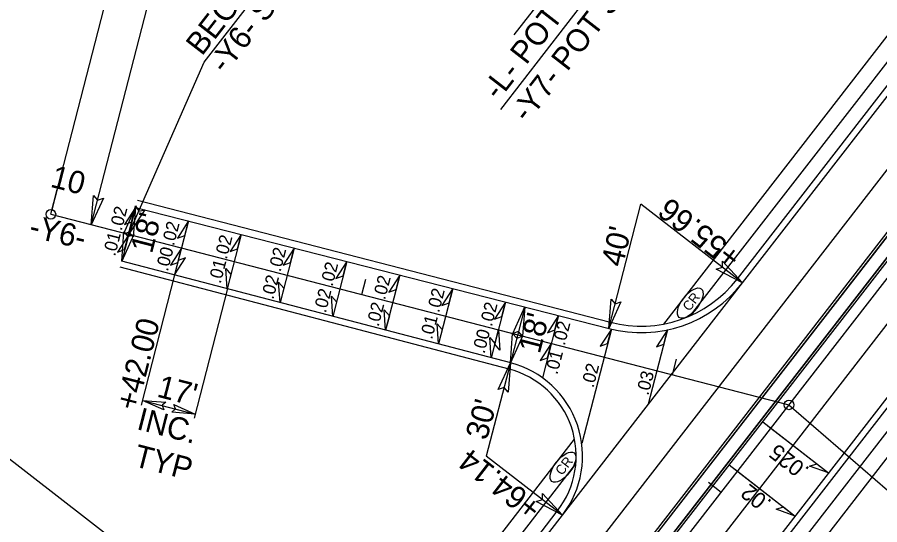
# Model space of a CAD drawing. Extents: x 2010838 to 2015151, y 441905 to 447792.
# Drawn here: x 2014110.1 to 2014378.8, y 445512.1 to 445670.1 of the extents above; entities that cross this region are included whole.
import ezdxf

# ---------------------------------------------------------------- set-up
doc = ezdxf.new("R2010")
doc.units = 0
for name, color, linetype in [('A-Wall-Blow', 7, 'Continuous'), ('A-Wall-Comp', 7, 'Continuous'), ('B-Border', 7, 'Continuous'), ('C-Building', 7, 'Continuous'), ('C-CURB STOPS', 7, 'Continuous'), ('C-EOP 1', 7, 'Continuous'), ('C-Grave Plots', 7, 'Continuous'), ('CLRD', 7, 'Continuous'), ('Cont-2-Lidar', 7, 'Continuous'), ('Default_10ft_LIDAR_Contou', 7, 'Continuous'), ('Default_2FT_LIDAR_Contour', 7, 'Continuous'), ('HATCH', 7, 'Continuous'), ('s-Existing Major', 7, 'Continuous'), ('S-Existing Minor', 7, 'Continuous'), ('S-overhead electric', 7, 'Continuous'), ('TEXT-LG', 7, 'Continuous'), ('TEXT-MED', 7, 'Continuous'), ('X4', 7, 'Continuous')]:
    doc.layers.add(name, color=color, linetype=linetype)

msp = doc.modelspace()

# ---------------------------------------------------------------- linework, layer by layer
at = {"layer": 'A-Wall-Blow'}
for p, q in [((2014146.98, 445610.86), (2014144.76, 445602.25)), ((2014146.98, 445610.86), (2014144.82, 445602.47)), ((2014163.45, 445606.65), (2014159.12, 445589.85)), ((2014144.76, 445602.25), (2014142.67, 445594.15)), ((2014179.92, 445602.44), (2014175.56, 445585.55)), ((2014196.39, 445598.23), (2014192.01, 445581.25)), ((2014212.86, 445594.02), (2014208.46, 445576.95)), ((2014229.33, 445589.81), (2014224.91, 445572.65)), ((2014245.8, 445585.6), (2014241.35, 445568.35)), ((2014262.27, 445581.38), (2014257.8, 445564.05)), ((2014278.74, 445577.17), (2014273.75, 445557.82)), ((2014295.22, 445572.97), (2014286.01, 445537.31)), ((2014312.72, 445572.75), (2014306.73, 445549.56)), ((2014342.38, 445544.12), (2014362.92, 445528.18)), ((2014331.96, 445530.68), (2014352.5, 445514.75))]:
    msp.add_line(p, q, dxfattribs=at)
at = {"layer": 'A-Wall-Comp'}
for p, q in [((2014343.96, 445542.89), (2014362.92, 445528.18)), ((2014333.54, 445529.46), (2014352.5, 445514.75))]:
    msp.add_line(p, q, dxfattribs=at)
for points in [[(2014146.98, 445610.86), (2014143.55, 445605.55), (2014145.83, 445606.38)], [(2014163.45, 445606.65), (2014160.02, 445601.34), (2014162.3, 445602.17)], [(2014144.76, 445602.25), (2014141.32, 445596.94), (2014143.6, 445597.77)], [(2014179.92, 445602.44), (2014176.49, 445597.13), (2014178.77, 445597.96)], [(2014161.28, 445598.23), (2014157.84, 445592.92), (2014160.12, 445593.75)], [(2014196.39, 445598.23), (2014192.96, 445592.92), (2014195.24, 445593.75)], [(2014159.12, 445589.85), (2014162.55, 445595.16), (2014160.27, 445594.33)], [(2014212.86, 445594.02), (2014209.43, 445588.71), (2014211.71, 445589.54)], [(2014175.56, 445585.55), (2014175.13, 445591.86), (2014176.72, 445590.03)], [(2014229.33, 445589.81), (2014225.9, 445584.5), (2014228.18, 445585.33)], [(2014192.01, 445581.25), (2014191.57, 445587.56), (2014193.17, 445585.73)], [(2014208.46, 445576.95), (2014208.02, 445583.26), (2014209.61, 445581.43)], [(2014245.8, 445585.6), (2014242.37, 445580.29), (2014244.65, 445581.12)], [(2014262.27, 445581.38), (2014258.84, 445576.07), (2014261.12, 445576.91)], [(2014224.91, 445572.65), (2014224.47, 445578.96), (2014226.06, 445577.13)], [(2014278.74, 445577.17), (2014275.31, 445571.86), (2014277.59, 445572.7)], [(2014241.35, 445568.35), (2014240.92, 445574.66), (2014242.51, 445572.83)], [(2014260.04, 445572.74), (2014260.48, 445566.43), (2014258.89, 445568.26)], [(2014295.22, 445572.97), (2014291.78, 445567.66), (2014294.06, 445568.49)], [(2014312.72, 445572.75), (2014309.28, 445567.44), (2014311.56, 445568.27)], [(2014257.8, 445564.05), (2014257.36, 445570.36), (2014258.96, 445568.52)], [(2014276.5, 445568.49), (2014273.07, 445563.18), (2014275.35, 445564.02)], [(2014362.92, 445528.18), (2014356.95, 445530.28), (2014359.27, 445531.02)], [(2014352.5, 445514.75), (2014346.54, 445516.85), (2014348.85, 445517.58)]]:
    msp.add_lwpolyline(points, close=True, dxfattribs=at)
at = {"layer": 'B-Border'}
msp.add_line((2014279.97, 445515.05), (2014336.06, 445587.37), dxfattribs=at)
at = {"layer": 'C-Building'}
for p, q in [((2014217.44, 445583.74), (2014218.69, 445588.58)), ((2014314.27, 445558.75), (2014315.52, 445563.59)), ((2014329.41, 445522.09), (2014325.46, 445525.16)), ((2014329.41, 445522.09), (2014325.46, 445525.16))]:
    msp.add_line(p, q, dxfattribs=at)
at = {"layer": 'C-CURB STOPS'}
for p, q in [((2014244.85, 445426.12), (2014703.05, 446016.93)), ((2014703.05, 446016.93), (2014244.85, 445426.12)), ((2014706.21, 446014.48), (2014313.99, 445508.74)), ((2014313.99, 445508.74), (2014706.21, 446014.48))]:
    msp.add_line(p, q, dxfattribs=at)
at = {"layer": 'C-EOP 1'}
msp.add_line((2014120.61, 445608.72), (2014122.61, 445616.47), dxfattribs=at)
at = {"layer": 'CLRD'}
for p, q in [((2014251.18, 445421.22), (2014766.2, 446085.3)), ((2014251.18, 445421.22), (2014746.42, 446059.8)), ((2014120.61, 445608.72), (2014350.57, 445549.38)), ((2014120.61, 445608.72), (2014350.57, 445549.38))]:
    msp.add_line(p, q, dxfattribs=at)
at = {"layer": 'Default_10ft_LIDAR_Contou'}
for p, q in [((2014264.94, 445664.67), (2014332.35, 445751.6)), ((2014337.54, 445740.52), (2014260.65, 445641.37)), ((2014120.99, 445610.17), (2014139.82, 445683.16)), ((2014133.21, 445605.47), (2014151.75, 445677.32)), ((2014249.99, 445422.14), (2014026.73, 445595.29)), ((2014350.57, 445549.38), (2014471.01, 445444.95))]:
    msp.add_line(p, q, dxfattribs=at)
for centre in [(2014120.61, 445608.72), (2014350.57, 445549.38)]:
    msp.add_circle(centre, 1.5, dxfattribs=at)
at = {"layer": 'HATCH'}
for p, q in [((2014234.78, 445433.94), (2014567.14, 445862.49)), ((2014244.26, 445426.58), (2014432.8, 445669.69)), ((2014314.58, 445508.28), (2014437.15, 445666.32)), ((2014324.07, 445500.93), (2014446.63, 445658.97))]:
    msp.add_line(p, q, dxfattribs=at)
at = {"layer": 's-Existing Major'}
for points in [[(2014136.96, 445613.8), (2014133.21, 445605.47), (2014133.92, 445614.63), (2014135.18, 445613.12)], [(2014143.23, 445602.54), (2014146.98, 445610.86), (2014146.27, 445601.7), (2014145.01, 445603.21)], [(2014149.85, 445610.09), (2014144.82, 445602.47), (2014146.99, 445611.4), (2014147.99, 445609.71)], [(2014146.42, 445602.48), (2014142.67, 445594.15), (2014143.38, 445603.32), (2014144.64, 445601.8)], [(2014329.9, 445594.11), (2014336.06, 445587.37), (2014327.93, 445591.66), (2014329.82, 445592.22)], [(2014298.21, 445581.48), (2014294.46, 445573.16), (2014295.17, 445582.32), (2014296.43, 445580.81)], [(2014264.51, 445571.59), (2014268.26, 445579.92), (2014267.55, 445570.75), (2014266.29, 445572.27)], [(2014267.51, 445570.81), (2014263.76, 445562.49), (2014264.47, 445571.65), (2014265.74, 445570.14)], [(2014260.01, 445554.16), (2014263.76, 445562.49), (2014263.05, 445553.32), (2014261.79, 445554.84)], [(2014155.82, 445547.83), (2014149.12, 445550.74), (2014156.45, 445550.27), (2014155.26, 445549.24)], [(2014158.92, 445549.52), (2014165.59, 445546.53), (2014158.25, 445547.08), (2014159.46, 445548.1)], [(2014273.81, 445521.79), (2014279.97, 445515.05), (2014271.84, 445519.34), (2014273.73, 445519.9)]]:
    msp.add_lwpolyline(points, close=True, dxfattribs=at)
at = {"layer": 'S-Existing Minor'}
for p, q in [((2014168.34, 445656.09), (2014235.22, 445742.33)), ((2014144.82, 445602.47), (2014168.34, 445656.09)), ((2014294.46, 445573.16), (2014304.45, 445611.89)), ((2014336.06, 445587.37), (2014304.45, 445611.89)), ((2014159.12, 445589.85), (2014148.74, 445549.26)), ((2014175.59, 445585.64), (2014165.26, 445545.24)), ((2014268.26, 445579.92), (2014263.76, 445562.49)), ((2014263.76, 445562.49), (2014256.27, 445533.44)), ((2014149.12, 445550.74), (2014165.59, 445546.53)), ((2014279.97, 445515.05), (2014256.27, 445533.44))]:
    msp.add_line(p, q, dxfattribs=at)
at = {"layer": 'S-overhead electric'}
for p, q in [((2014336.06, 445587.37), (2014411.9, 445685.17)), ((2014335.44, 445492.74), (2014456.6, 445648.98)), ((2014146.98, 445610.86), (2014294.54, 445573.13)), ((2014263.86, 445562.46), (2014142.67, 445594.15)), ((2014223.72, 445442.52), (2014279.97, 445515.05))]:
    msp.add_line(p, q, dxfattribs=at)
for centre, radius, start, end in [((2014304.45, 445611.89), 40, 255.5311, 322.2051), ((2014256.27, 445533.44), 30, 322.2051, 75.5311)]:
    msp.add_arc(centre, radius, start, end, dxfattribs=at)
at = {"layer": 'TEXT-LG'}
for p, q in [((2014311.57, 445574.56), (2014415.7, 445708.83)), ((2014319.93, 445577.18), (2014416.1, 445701.18)), ((2014344.55, 445485.73), (2014481.09, 445661.79)), ((2014340.6, 445488.79), (2014472.73, 445659.17)), ((2014214.63, 445449.56), (2014283.77, 445538.71)), ((2014218.58, 445446.5), (2014284.17, 445531.07))]:
    msp.add_line(p, q, dxfattribs=at)
at = {"layer": 'TEXT-MED'}
for p, q in [((2014334.48, 445588.6), (2014410.32, 445686.4)), ((2014337.04, 445491.55), (2014458.18, 445647.75)), ((2014147.57, 445613.13), (2014294.96, 445575.09)), ((2014263.35, 445560.53), (2014142.16, 445592.22)), ((2014222.14, 445443.74), (2014278.39, 445516.28))]:
    msp.add_line(p, q, dxfattribs=at)
for centre, radius, start, end in [((2014304.45, 445611.89), 38, 255.5311, 322.2051), ((2014256.27, 445533.44), 28, 322.2051, 75.5311)]:
    msp.add_arc(centre, radius, start, end, dxfattribs=at)
at = {"layer": 'X4'}
for centre in [(2014319.81, 445581.07), (2014280.16, 445529.97)]:
    msp.add_ellipse(centre, major_axis=(3.43, 4.44), ratio=0.462467, dxfattribs=at)

# ---------------------------------------------------------------- texts
at = {"layer": 'A-Wall-Blow'}
for s, height, rotation, p in [('.02', 4, 75.5311, (2014142.66, 445603.42)), ('.02', 4, 75.5311, (2014158.92, 445598.72)), ('.01', 4, 75.5311, (2014140.61, 445595.48)), ('.02', 4, 75.5311, (2014175.39, 445594.51)), ('.00', 4, 75.5311, (2014157.04, 445590.77)), ('.02', 4, 75.5311, (2014192.15, 445590.62)), ('.01', 4, 75.5311, (2014173.49, 445586.97)), ('.02', 4, 75.5311, (2014208.33, 445586.08)), ('.02', 4, 75.5311, (2014189.91, 445582.03)), ('.02', 4, 75.5311, (2014224.7, 445581.9)), ('.02', 4, 75.5311, (2014241.54, 445577.9)), ('.02', 4, 75.5311, (2014206.24, 445577.81)), ('.02', 4, 75.5311, (2014222.69, 445573.56)), ('.02', 4, 75.5311, (2014257.98, 445573.59)), ('.01', 4, 75.5311, (2014239.38, 445569.58)), ('.02', 4, 75.5311, (2014280.68, 445567.67)), ('.00', 4, 75.5311, (2014255.67, 445565.15)), ('.01', 4, 75.5311, (2014278.38, 445558.62)), ('.02', 4, 75.5311, (2014289.64, 445554.51)), ('.03', 4, 75.5311, (2014306.73, 445552.14)), ('.025', 5, 142.2051, (2014357.22, 445529.56)), ('.02', 5, 142.2051, (2014345.48, 445519.39))]:
    msp.add_text(s, height=height, rotation=rotation, dxfattribs=at).set_placement(p)
at = {"layer": 'C-Grave Plots'}
for s, rotation, p in [('BEGIN CONSTRUCTION', 52.1339, (2014167.67, 445657.79)), ('-Y6- STA. 10+25.00', 52.1339, (2014174.91, 445652.16)), ('+55.66', 142.2051, (2014336.23, 445596.57)), ("18'", 75.5311, (2014152.09, 445596.26)), ("40'", 76.8578, (2014298.76, 445592.06)), ("18'", 75.5311, (2014272.9, 445565.06)), ('+42.00', 75.6507, (2014147.45, 445547.29)), ("17'", 345.5608, (2014153.34, 445552)), ("30'", 74.5695, (2014256.4, 445538.1)), ('INC. ', 345.5608, (2014147.05, 445541.88)), ('TYP', 345.5608, (2014146.05, 445530.39)), ('+64.14', 142.2051, (2014274.02, 445518.4))]:
    msp.add_text(s, height=7, rotation=rotation, dxfattribs=at).set_placement(p)
at = {"layer": 'Cont-2-Lidar'}
msp.add_text('-Y6-', height=7, rotation=346.8406, dxfattribs=at).set_placement((2014113.45, 445601.83))
at = {"layer": 'Default_10ft_LIDAR_Contou'}
for s, p in [('-L- POT Sta. 45+25.53=', (2014260.08, 445643.93)), ('-Y7- POT Sta.  12+27.52', (2014269.07, 445636.96))]:
    msp.add_text(s, height=7, rotation=52.2051, dxfattribs=at).set_placement(p)
at = {"layer": 'Default_2FT_LIDAR_Contour'}
msp.add_text('10', height=7, rotation=345.5311, dxfattribs=at).set_placement((2014120.15, 445617.35))
at = {"layer": 'X4'}
for p in [(2014319.53, 445578.31), (2014279.88, 445527.2)]:
    msp.add_text('CR', height=3, rotation=52.2869, dxfattribs=at).set_placement(p)

doc.saveas('drawing.dxf')
